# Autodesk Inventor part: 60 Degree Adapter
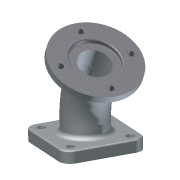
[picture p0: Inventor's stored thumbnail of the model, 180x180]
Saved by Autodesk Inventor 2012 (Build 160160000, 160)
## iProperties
Created: 2010-11
Part Number: 60 Degree Adapter
Material: Default
Document SubType Name: Modeling
Designer: Beta-8540w
Density: 1 g/cm^3
Author: Beta-8540w
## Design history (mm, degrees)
sketch "Sketch1"
  geometry: L1 (50, 50)-(50, -50); L2 (50, -50)-(-50, -50); L3 (-50, -50)-(-50, 50); L4 (-50, 50)-(50, 50); C1 r 28 at (0, 0); C2 r 20 at (0, 0); 2 further points
  constraints: 8 end point, 3 coincident, 2 centre point, 1 horizontal, 9 other
  dimensions: "d0" = 100 distance of L3.end L1.start; "d8" = 8 radial gap between concentric circles of C1 C2; "d17" = 40 diameter of C2
extrude "Extrusion1" new body sketch "Sketch1" distance "d1" = 15; taper "d2" = 0 deg
sketch "Sketch2"
  geometry: L1 (0, 0)-(0, 30); L2 (-13.397, 80)-(-28.397, 105.981); A1 r 100 centre (-100, 30) between (0, 30) and (-13.397, 80)
  constraints: 4 end point, 2 point on circle, 2 tangent, 1 centre point, 1 vertical
  dimensions: "d3" = 30 distance of L1.start L1.end; "d4" = 30 distance of L2.start L2.end; "d5" = 150 deg angle of L1 L2; "d6" = 100 radius of A1
workplane "Work Plane1"
sketch "Sketch3"
  geometry: C1 r 55 at (0, 0); 2 further points
  constraints: 1 centre point, 1 coincident
  dimensions: "d9" = 110 diameter of C1
extrude "Extrusion2" join sketch "Sketch3" distance "d10" = 10; taper "d11" = 0 deg
sweep "Sweep1" dims "d12" = 0
sweep "Sweep2" dims "d13" = 0
fillet "Fillet1" dims "d14" = 14, "d15" = 6, "d16" = 2
hole "Hole1" diameter "d20" = 11; stored, may be unused: countersink angle "d24" = 90 deg, drill point angle "d26" = 118 deg; dims "d18" = 10, "d19" = 10, "d21" = 6, "d22" = 20, "d23" = 2, "d25" = 8
hole "Hole2" diameter "d29" = 11; stored, may be unused: countersink angle "d33" = 90 deg, drill point angle "d35" = 118 deg; dims "d27" = 10, "d28" = 10, "d30" = 6, "d31" = 20, "d32" = 2, "d34" = 8
hole "Hole3" diameter "d38" = 11; stored, may be unused: countersink angle "d42" = 90 deg, drill point angle "d44" = 118 deg; dims "d36" = 10, "d37" = 10, "d39" = 6, "d40" = 20, "d41" = 2, "d43" = 8
hole "Hole4" diameter "d47" = 11; stored, may be unused: countersink angle "d51" = 90 deg, drill point angle "d53" = 118 deg; dims "d45" = 10, "d46" = 10, "d48" = 6, "d49" = 20, "d50" = 2, "d52" = 8
sketch "Sketch4" dims "d54" = 85
  geometry: L1 (0, 42.5)-(42.5, 0); L2 (42.5, 0)-(0, -42.5); L3 (0, -42.5)-(-42.5, 0); L4 (-42.5, 0)-(0, 42.5); C1 r 55 at (0, 0) reference; 3 further points
  constraints: 8 end point, 2 coincident, 1 vertical alignment, 11 other
hole "Hole5" sketch "Sketch4" at (0, 42.5), (42.5, 0), (0, -42.5), (-42.5, 0) diameter "d55" = 8.376; stored, may be unused: countersink angle "d59" = 90 deg, drill point angle "d61" = 118 deg; dims "d56" = 6, "d57" = 20, "d58" = 2, "d60" = 8
sketch "Sketch5"
  geometry: C1 r 55 at (0, 0) reference; C2 r 30 at (0, 0); 1 further point
  constraints: 1 centre point, 1 coincident
  dimensions: "d62" = 60 diameter of C2
extrude "Extrusion3" cut sketch "Sketch5" distance "d63" = 6; taper "d64" = 0 deg
sketch "Sketch6"
  geometry: C1 r 20 at (0, 0) reference; C2 r 30 at (0, 0); C3 r 33 at (0, 0)
  constraints: 2 centre point, 1 coincident
  dimensions: "d65" = 60 diameter of C2; "d66" = 3 radial gap between concentric circles of C3 C2
extrude "Extrusion4" cut sketch "Sketch6" distance "d67" = 3; taper "d68" = 0 deg
fillet "Fillet2" dims "d69" = 0.5
chamfer "Chamfer1" distance "d70" = 2; stored, may be unused: second distance "d71" = 2, angle "d72" = 45 deg
chamfer "Chamfer2" distance "d73" = 1; stored, may be unused: second distance "d74" = 2, angle "d75" = 45 deg
fillet "Fillet3" dims "d76" = 0.5
body "Solid1"
